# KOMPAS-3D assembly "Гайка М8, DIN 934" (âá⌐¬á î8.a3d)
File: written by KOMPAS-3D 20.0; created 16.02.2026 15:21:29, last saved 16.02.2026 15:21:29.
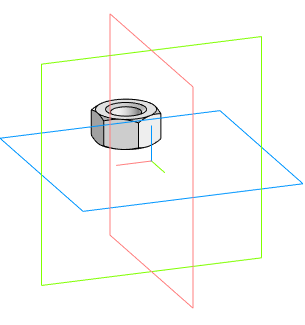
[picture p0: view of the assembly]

Document properties: Автор: admin; Полное имя файла: P:\INSTART\Технический отдел\ОР\Прочие задачи\КД на номенклатурный ряд\КД на типоразмеры дросселей\Сетевые дроссели ISF\ISF-4\Тип 1\ISF-132_256-4\0723\Новая папка\Гайка М8.a3d

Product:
- Part/product: Гайка М8  | designation DIN 934
  - Component [detail]: Hexagon regular nut ISO 4032 - M8  | source file: Hexagon regular nut ISO 4032 - M8.m3d

Referenced files in P:\INSTART\Технический отдел\ОР\Прочие задачи\КД на номенклатурный ряд\КД на типоразмеры дросселей\Сетевые дроссели ISF\ISF-4\Тип 1\ISF-132_256-4\0723\Новая папка\: Hexagon regular nut ISO 4032 - M8.m3d
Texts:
  DIN 934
